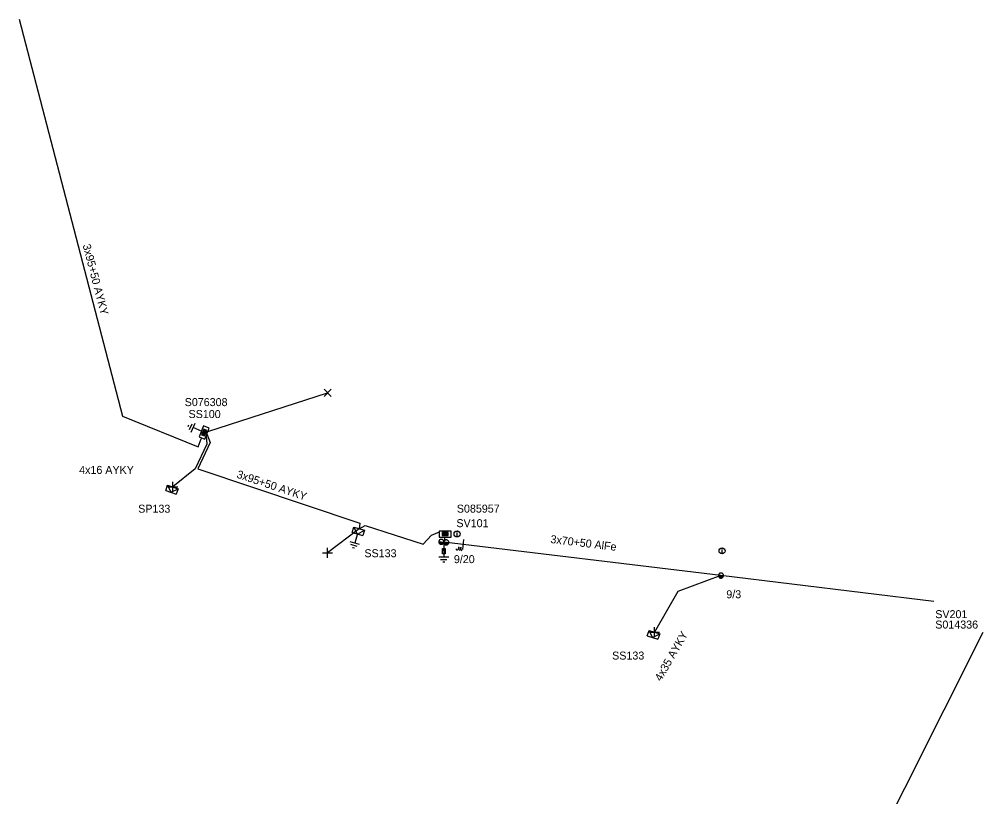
# Model space of a CAD drawing. Extents: x -717562 to -713845, y -1151196 to -1143903.
# Drawn here: x -714718.5 to -714598.1, y -1145580.5 to -1145483.3 of the extents above; entities that cross this region are included whole.
import ezdxf

# ---------------------------------------------------------------- set-up
doc = ezdxf.new("R2010")
doc.units = 0
for name, color, linetype in [('Vrstva 1', 7, 'Continuous'), ('Vrstva 10', 7, 'Continuous'), ('Vrstva 12', 7, 'Continuous'), ('Vrstva 13', 7, 'Continuous'), ('Vrstva 14', 7, 'Continuous'), ('Vrstva 15', 7, 'Continuous'), ('Vrstva 16', 7, 'Continuous'), ('Vrstva 18', 7, 'Continuous'), ('Vrstva 2', 7, 'Continuous'), ('Vrstva 28', 7, 'Continuous'), ('Vrstva 29', 7, 'Continuous'), ('Vrstva 30', 7, 'Continuous'), ('Vrstva 31', 7, 'Continuous'), ('Vrstva 33', 7, 'Continuous'), ('Vrstva 34', 7, 'Continuous'), ('Vrstva 36', 7, 'Continuous'), ('Vrstva 5', 7, 'Continuous'), ('Vrstva 52', 7, 'Continuous'), ('Vrstva 54', 7, 'Continuous'), ('Vrstva 59', 7, 'Continuous'), ('Vrstva 6', 7, 'Continuous'), ('Vrstva 8', 7, 'Continuous'), ('Vrstva 9', 7, 'Continuous')]:
    doc.layers.add(name, color=color, linetype=linetype)

# ---------------------------------------------------------------- blocks, each defined once
blk = doc.blocks.new('NN440')
at = {"layer": 'Vrstva 2'}
for points in [[(0.63, 0), (0.63, 0.06), (0.62, 0.13), (0.6, 0.19), (0.58, 0.25), (0.55, 0.31), (0.51, 0.37), (0.47, 0.42), (0.42, 0.46), (0.37, 0.51), (0.32, 0.54), (0.26, 0.57), (0.2, 0.59), (0.13, 0.61), (0.07, 0.62), (0, 0.63), (-0.06, 0.62), (-0.13, 0.61), (-0.19, 0.59), (-0.26, 0.57), (-0.31, 0.54), (-0.37, 0.51), (-0.42, 0.46), (-0.47, 0.42), (-0.51, 0.37), (-0.54, 0.31), (-0.57, 0.25), (-0.6, 0.19), (-0.62, 0.13), (-0.63, 0.06), (-0.63, 0), (-0.63, -0.07), (-0.62, -0.14), (-0.6, -0.2), (-0.57, -0.26), (-0.54, -0.32), (-0.51, -0.37), (-0.47, -0.43), (-0.42, -0.47), (-0.37, -0.51), (-0.31, -0.55), (-0.26, -0.58), (-0.19, -0.6), (-0.13, -0.62), (-0.06, -0.63), (0, -0.63), (0.07, -0.63), (0.13, -0.62), (0.2, -0.6), (0.26, -0.58), (0.32, -0.55), (0.37, -0.51), (0.42, -0.47), (0.47, -0.43), (0.51, -0.37), (0.55, -0.32), (0.58, -0.26), (0.6, -0.2), (0.62, -0.14), (0.63, -0.07), (0.63, 0)], [(-0.63, 0), (0.63, 0)], [(-0.6, -0.18), (0.57, -0.18)], [(-0.51, -0.32), (0.5, -0.32)], [(-0.37, -0.47), (0.35, -0.47)]]:
    blk.add_lwpolyline(points, dxfattribs=at)
blk = doc.blocks.new('NN450')
at = {"layer": 'Vrstva 2'}
for points in [[(0, 0), (0, 0.07), (-0.01, 0.13), (-0.03, 0.19), (-0.05, 0.25), (-0.08, 0.31), (-0.12, 0.37), (-0.16, 0.42), (-0.21, 0.46), (-0.26, 0.51), (-0.31, 0.54), (-0.37, 0.57), (-0.43, 0.59), (-0.5, 0.61), (-0.56, 0.62), (-0.63, 0.62), (-0.69, 0.62), (-0.75, 0.61), (-0.82, 0.59), (-0.88, 0.57), (-0.94, 0.54), (-0.99, 0.51), (-1.04, 0.46), (-1.09, 0.42), (-1.13, 0.37), (-1.17, 0.31), (-1.2, 0.25), (-1.22, 0.19), (-1.24, 0.13), (-1.25, 0.07), (-1.25, 0), (-1.25, -0.07), (-1.24, -0.13), (-1.22, -0.19), (-1.2, -0.25), (-1.17, -0.31), (-1.13, -0.37), (-1.09, -0.42), (-1.04, -0.46), (-0.99, -0.51), (-0.94, -0.54), (-0.88, -0.57), (-0.82, -0.59), (-0.75, -0.61), (-0.69, -0.62), (-0.62, -0.63), (-0.56, -0.62), (-0.5, -0.61), (-0.43, -0.59), (-0.37, -0.57), (-0.31, -0.54), (-0.26, -0.51), (-0.21, -0.46), (-0.16, -0.42), (-0.12, -0.37), (-0.08, -0.31), (-0.05, -0.25), (-0.03, -0.19), (-0.01, -0.13), (0, -0.07), (0, 0)], [(1.25, 0), (1.25, 0.07), (1.24, 0.13), (1.22, 0.19), (1.2, 0.25), (1.17, 0.31), (1.13, 0.37), (1.09, 0.42), (1.04, 0.46), (0.99, 0.51), (0.94, 0.54), (0.88, 0.57), (0.82, 0.59), (0.75, 0.61), (0.69, 0.62), (0.62, 0.62), (0.56, 0.62), (0.5, 0.61), (0.43, 0.59), (0.37, 0.57), (0.31, 0.54), (0.26, 0.51), (0.21, 0.46), (0.16, 0.42), (0.12, 0.37), (0.08, 0.31), (0.05, 0.25), (0.03, 0.19), (0.01, 0.13), (0, 0.07), (0, 0), (0, -0.07), (0.01, -0.13), (0.03, -0.19), (0.05, -0.25), (0.08, -0.31), (0.12, -0.37), (0.16, -0.42), (0.21, -0.46), (0.26, -0.51), (0.31, -0.54), (0.37, -0.57), (0.43, -0.59), (0.5, -0.61), (0.56, -0.62), (0.63, -0.63), (0.69, -0.62), (0.75, -0.61), (0.82, -0.59), (0.88, -0.57), (0.94, -0.54), (0.99, -0.51), (1.04, -0.46), (1.09, -0.42), (1.13, -0.37), (1.17, -0.31), (1.2, -0.25), (1.22, -0.19), (1.24, -0.13), (1.25, -0.07), (1.25, 0)], [(-1.25, 0), (1.25, 0)], [(-1.23, -0.16), (-0.02, -0.16)], [(-1.16, -0.32), (-0.09, -0.32)], [(-1.03, -0.47), (-0.22, -0.47)], [(0.02, -0.16), (1.23, -0.16)], [(0.09, -0.32), (1.16, -0.32)], [(0.22, -0.47), (1.03, -0.47)]]:
    blk.add_lwpolyline(points, dxfattribs=at)
blk = doc.blocks.new('NN840')
at = {"layer": 'Vrstva 15'}
for points in [[(0, 0.62), (0, -0.63)], [(-0.75, -0.71), (-0.75, -0.66)], [(-0.73, -0.76), (-0.75, -0.71)], [(-0.66, -0.8), (-0.73, -0.76)], [(-0.63, -0.8), (-0.66, -0.8)], [(-0.56, -0.76), (-0.63, -0.8)], [(-0.54, -0.71), (-0.56, -0.76)], [(-0.54, -0.38), (-0.54, -0.71)], [(-0.33, -0.38), (-0.33, -0.8)], [(-0.33, -0.64), (-0.13, -0.38)], [(-0.26, -0.56), (-0.09, -0.8)]]:
    blk.add_lwpolyline(points, dxfattribs=at)
blk = doc.blocks.new('NN770')
at = {"layer": 'Vrstva 10'}
for p, q in [((0, 0.19), (0, 0.26)), ((0, -0.28), (0, 0.11))]:
    blk.add_line(p, q, dxfattribs=at)
blk.add_circle((0, -0.01), 0.375, dxfattribs=at)
blk = doc.blocks.new('NN800')
at = {"layer": 'Vrstva 1'}
for points in [[(-0.44, 0.44), (0.44, -0.44)], [(-0.44, -0.44), (0.44, 0.44)]]:
    blk.add_lwpolyline(points, dxfattribs=at)
blk = doc.blocks.new('NN820')
at = {"layer": 'Vrstva 13'}
for points in [[(0, 0), (0, -1.05)], [(-0.16, -0.81), (0.16, -0.81)], [(-0.16, -1.47), (-0.16, -0.81)], [(0, -1.05), (-0.06, -0.93)], [(0, -1.05), (0.06, -0.93)], [(0.16, -0.81), (0.16, -1.47)], [(0.16, -1.47), (-0.16, -1.47)], [(0, -1.47), (0, -1.87)]]:
    blk.add_lwpolyline(points, dxfattribs=at)
blk = doc.blocks.new('NN620')
at = {"layer": 'Vrstva 8'}
for points in [[(0.75, 0), (-0.75, 0)], [(-0.75, 0), (-0.75, -0.75)], [(0.75, -0.75), (0.75, 0)], [(-0.75, -0.75), (0.75, -0.75)], [(0.37, -0.18), (-0.38, -0.18)], [(-0.38, -0.18), (-0.38, -0.56)], [(-0.38, -0.56), (0.37, -0.56)], [(0.32, -0.23), (-0.33, -0.23)], [(-0.33, -0.23), (-0.33, -0.51)], [(-0.33, -0.51), (0.32, -0.51)], [(0.27, -0.27), (-0.28, -0.27)], [(-0.28, -0.27), (-0.28, -0.46)], [(-0.28, -0.46), (0.27, -0.46)], [(0.23, -0.32), (-0.23, -0.32)], [(-0.23, -0.32), (-0.23, -0.42)], [(-0.23, -0.42), (0.23, -0.42)], [(-0.19, -0.37), (0.19, -0.37)], [(0.23, -0.42), (0.23, -0.32)], [(0.27, -0.46), (0.27, -0.27)], [(0.32, -0.51), (0.32, -0.23)], [(0.37, -0.56), (0.37, -0.18)]]:
    blk.add_lwpolyline(points, dxfattribs=at)
blk = doc.blocks.new('NN630')
at = {"layer": 'Vrstva 9'}
for points in [[(0, -0.7), (-0.7, 0)], [(-0.7, -0.7), (-0.7, 0), (0.7, 0), (0.7, -0.7)], [(-0.7, -0.7), (0.7, -0.7)], [(0, -0.7), (0.7, 0)]]:
    blk.add_lwpolyline(points, dxfattribs=at)
blk = doc.blocks.new('NN810')
at = {"layer": 'Vrstva 14'}
for points in [[(0, -0.64), (0, -1.89)], [(0.63, -1.89), (-0.62, -1.89)], [(0.39, -2.2), (-0.4, -2.2)], [(0, -2.52), (-0.12, -2.52)], [(0.14, -2.52), (0, -2.52)]]:
    blk.add_lwpolyline(points, dxfattribs=at)

msp = doc.modelspace()

# ---------------------------------------------------------------- linework, layer by layer
at = {"layer": 'Vrstva 1'}
for points in [[(-714604.23, -1145556.1), (-714630.84, -1145552.85), (-714665.48, -1145548.67)], [(-714598.13, -1145559.99), (-714612.77, -1145589.2), (-714628.77, -1145621.09), (-714639.6, -1145642.51)]]:
    msp.add_lwpolyline(points, dxfattribs=at)
at = {"layer": 'Vrstva 5'}
for points in [[(-714718.53, -1145483.28), (-714705.65, -1145532.91), (-714696.17, -1145536.77), (-714695.82, -1145535.76), (-714695.66, -1145535.63)], [(-714695.08, -1145535.11), (-714694.68, -1145536.19), (-714696.23, -1145539.52), (-714675.97, -1145546.32), (-714676.06, -1145546.99), (-714675.29, -1145546.59), (-714668.04, -1145548.92), (-714667, -1145547.8), (-714666, -1145547.4)], [(-714665.33, -1145547.99), (-714665.48, -1145548.67)]]:
    msp.add_lwpolyline(points, dxfattribs=at)
at = {"layer": 'Vrstva 52'}
for points in [[(-714695.18, -1145535.37), (-714695.11, -1145536.41), (-714696.54, -1145539.49), (-714699.33, -1145541.77)], [(-714630.84, -1145552.85), (-714636.24, -1145554.83), (-714639.16, -1145559.93)]]:
    msp.add_lwpolyline(points, dxfattribs=at)
at = {"layer": 'Vrstva 59'}
for points in [[(-714694.97, -1145534.83), (-714680, -1145530)], [(-714676.06, -1145546.99), (-714680, -1145550)]]:
    msp.add_lwpolyline(points, dxfattribs=at)

# ---------------------------------------------------------------- block references
at = {"layer": 'Vrstva 13'}
for name, p, xscale, yscale, rotation in [('NN450', (-714665.48, -1145548.67), 0.4999999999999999, 0.5, -6.887994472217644), ('NN440', (-714630.84, -1145552.85), 0.5000000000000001, 0.5000000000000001, -6.887994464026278)]:
    msp.add_blockref(name, p, dxfattribs=dict(at, xscale=xscale, yscale=yscale, rotation=rotation))
at = {"layer": 'Vrstva 15'}
for p, rotation in [((-714695.08, -1145535.11), -113.82426107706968), ((-714676.06, -1145546.99), -16.722813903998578)]:
    msp.add_blockref('NN810', p, dxfattribs=dict(at, rotation=rotation))
msp.add_blockref('NN810', (-714665.48, -1145548.67), dxfattribs=at)
at = {"layer": 'Vrstva 16'}
msp.add_blockref('NN820', (-714665.48, -1145548.67), dxfattribs=at)
at = {"layer": 'Vrstva 18', "rotation": -6.88919996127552}
msp.add_blockref('NN840', (-714663.08, -1145548.96), dxfattribs=at)
at = {"layer": 'Vrstva 28', "rotation": -112.15578891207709}
msp.add_blockref('NN620', (-714695.08, -1145535.11), dxfattribs=at)
at = {"layer": 'Vrstva 28'}
msp.add_blockref('NN620', (-714665.3, -1145547.3), dxfattribs=at)
at = {"layer": 'Vrstva 31'}
for p, rotation in [((-714699.33, -1145541.77), -19.68580846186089), ((-714676.06, -1145546.99), -16.68154444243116), ((-714639.16, -1145559.93), -18.43495007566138)]:
    msp.add_blockref('NN630', p, dxfattribs=dict(at, rotation=rotation))
at = {"layer": 'Vrstva 34'}
msp.add_blockref('NN800', (-714680, -1145530), dxfattribs=at)
at = {"layer": 'Vrstva 34', "rotation": 45}
for p in [(-714699.33, -1145541.77), (-714680, -1145550), (-714639.16, -1145559.93)]:
    msp.add_blockref('NN800', p, dxfattribs=at)
at = {"layer": 'Vrstva 36'}
for p in [(-714663.82, -1145547.64), (-714630.71, -1145549.75)]:
    msp.add_blockref('NN770', p, dxfattribs=at)

# ---------------------------------------------------------------- texts
at = {"layer": 'Vrstva 12'}
for s, p in [('9/20', (-714664.22, -1145551.3)), ('9/3', (-714630.17, -1145555.69))]:
    msp.add_text(s, height=1, dxfattribs=at).set_placement(p)
at = {"layer": 'Vrstva 2'}
msp.add_text('3x70+50 AlFe', height=1, rotation=353.111, dxfattribs=at).set_placement((-714652.19, -1145548.77))
at = {"layer": 'Vrstva 29'}
for s, p in [('S076308', (-714697.86, -1145531.66)), ('S085957', (-714663.85, -1145544.98)), ('S014336', (-714604.06, -1145559.48))]:
    msp.add_text(s, height=1, dxfattribs=at).set_placement(p)
at = {"layer": 'Vrstva 30'}
msp.add_text('SS100', height=1, rotation=359.88, dxfattribs=at).set_placement((-714697.38, -1145533.15))
for s, p in [('SV101', (-714663.9, -1145546.8)), ('SV201', (-714604.06, -1145558.18))]:
    msp.add_text(s, height=1, dxfattribs=at).set_placement(p)
at = {"layer": 'Vrstva 33'}
for s, p in [('SP133', (-714703.67, -1145544.99)), ('SS133', (-714675.4, -1145550.56)), ('SS133', (-714644.44, -1145563.36))]:
    msp.add_text(s, height=1, dxfattribs=at).set_placement(p)
at = {"layer": 'Vrstva 54'}
msp.add_text('4x16 AYKY', height=1, dxfattribs=at).set_placement((-714711.05, -1145540.14))
msp.add_text('4x35 AYKY', height=1, rotation=60.149, dxfattribs=at).set_placement((-714638.33, -1145566.14))
at = {"layer": 'Vrstva 6'}
for rotation, p in [(284.548, (-714710.62, -1145511.53)), (341.461, (-714691.44, -1145540.59))]:
    msp.add_text('3x95+50 AYKY', height=1, rotation=rotation, dxfattribs=at).set_placement(p)

doc.saveas('drawing.dxf')
